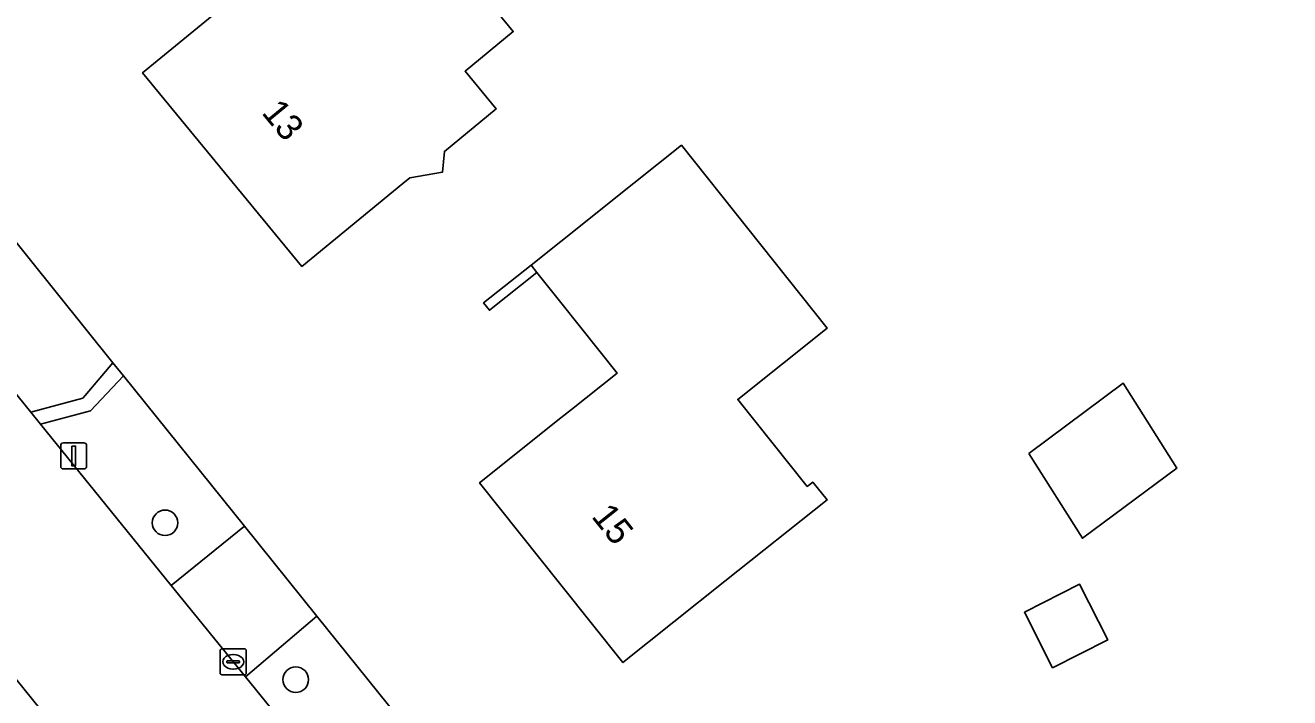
# Model space of a CAD drawing. Extents: x 162417 to 163722, y 384268 to 385417.
# Drawn here: x 163479.48 to 163527.92, y 384789.06 to 384814.82 of the extents above; entities that cross this region are included whole.
import ezdxf

# ---------------------------------------------------------------- set-up
doc = ezdxf.new("R2010")
doc.units = 0
for name, color, linetype in [('IMGEO_Berm_groen', 7, 'Continuous'), ('IMGEO_Boom', 7, 'Continuous'), ('IMGEO_Erf', 7, 'Continuous'), ('IMGEO_Kolk', 7, 'Continuous'), ('IMGEO_Lichtmast', 7, 'Continuous'), ('IMGEO_Muur', 7, 'Continuous'), ('IMGEO_Pand', 7, 'Continuous'), ('IMGEO_Pand_nummerreeks', 7, 'Continuous'), ('IMGEO_Rijbaan_lokaal_gesloten', 7, 'Continuous'), ('IMGEO_Voetpad_open', 7, 'Continuous')]:
    doc.layers.add(name, color=color, linetype=linetype)

msp = doc.modelspace()

# ---------------------------------------------------------------- linework, layer by layer
at = {"layer": 'IMGEO_Berm_groen'}
for points in [[(163478.544, 384807.238), (163475.697, 384804.93), (163479.692, 384800.002), (163481.684, 384800.531), (163481.772, 384800.634), (163482.841, 384801.894)], [(163483.251, 384801.384), (163481.978, 384800.048), (163480.069, 384799.537), (163485.075, 384793.362), (163487.878, 384795.63)], [(163490.658, 384792.176), (163487.913, 384789.862), (163497.934, 384777.502), (163500, 384778.506), (163501.192, 384779.094), (163500, 384780.574)]]:
    msp.add_lwpolyline(points, close=True, dxfattribs=at)
msp.add_lwpolyline([(163500.768, 384762.843), (163498.152, 384766.179), (163475.492, 384794.264)], dxfattribs=at)
at = {"layer": 'IMGEO_Boom'}
for centre in [(163484.838, 384795.758), (163489.844, 384789.748)]:
    msp.add_circle(centre, 0.489, dxfattribs=at)
at = {"layer": 'IMGEO_Erf'}
for points in [[(163495.537, 384809.986), (163495.46, 384809.189), (163494.212, 384808.981), (163493.944, 384808.76), (163490.082, 384805.583), (163483.976, 384813.003), (163487.76, 384816.118), (163489.245, 384817.34), (163488.402, 384818.365), (163487.45, 384818.206), (163487.125, 384818.602), (163487.08, 384818.657), (163484.691, 384821.56), (163488.553, 384824.737), (163492.118, 384827.671), (163496.846, 384821.926), (163494.033, 384819.612), (163498.173, 384814.58), (163496.328, 384813.061), (163497.518, 384811.616)], [(163506.285, 384793.52), (163502.375, 384790.402), (163500, 384793.381), (163496.883, 384797.291), (163500, 384799.776), (163500.406, 384800.099), (163502.157, 384801.496), (163500, 384804.2), (163499.081, 384805.352), (163497.265, 384803.905), (163497.042, 384804.185), (163498.857, 384805.632), (163500, 384806.543), (163502.796, 384808.772), (163504.62, 384810.226), (163510.205, 384803.221), (163506.776, 384800.487), (163509.436, 384797.15), (163509.651, 384797.321), (163510.196, 384796.638)], [(163517.928, 384798.42), (163521.541, 384801.103), (163523.592, 384797.848), (163519.979, 384795.165)], [(163519.87, 384793.404), (163520.949, 384791.273), (163518.835, 384790.203), (163517.756, 384792.333)]]:
    msp.add_lwpolyline(points, close=True, dxfattribs=at)
msp.add_lwpolyline([(163463.926, 384825.396), (163473.971, 384812.925), (163477.644, 384808.357), (163478.544, 384807.238), (163482.841, 384801.894), (163483.251, 384801.384), (163487.878, 384795.63), (163490.658, 384792.176), (163500, 384780.574), (163501.192, 384779.094), (163504.115, 384775.46), (163512.497, 384764.123), (163515.109, 384762.248), (163516.079, 384762.732), (163516.622, 384762.752), (163544.387, 384777.107), (163568.118, 384789.259), (163565.372, 384794.06), (163550.928, 384821.281)], dxfattribs=at)
at = {"layer": 'IMGEO_Kolk'}
for p, q in [((163486.948, 384790.005), (163486.948, 384790.857)), ((163487.023, 384790.931), (163487.875, 384790.931)), ((163487.436, 384790.711), (163487.461, 384790.711)), ((163487.949, 384790.857), (163487.949, 384790.005)), ((163487.207, 384790.425), (163487.207, 384790.437)), ((163487.645, 384790.388), (163487.247, 384790.388)), ((163487.25, 384790.474), (163487.648, 384790.474)), ((163487.459, 384790.151), (163487.434, 384790.151)), ((163487.691, 384790.437), (163487.691, 384790.425)), ((163487.875, 384789.931), (163487.023, 384789.931))]:
    msp.add_line(p, q, dxfattribs=at)
for points in [[(163486.948, 384790.005), (163486.948, 384790.857)], [(163487.023, 384790.931), (163487.875, 384790.931)], [(163487.949, 384790.857), (163487.949, 384790.005)], [(163487.875, 384789.931), (163487.023, 384789.931)]]:
    msp.add_lwpolyline(points, dxfattribs=at)
for centre, radius, start, end in [((163487.025, 384790.855), 0.0765, 91.552, 178.448), ((163487.025, 384790.855), 0.0765, 91.552, 178.448), ((163487.873, 384790.855), 0.0765, 1.552, 88.448), ((163487.873, 384790.855), 0.0765, 1.552, 88.448), ((163487.247, 384790.434), 0.0403, 85.8775, 175.7526), ((163487.244, 384790.424), 0.0366, 178.938, 274.7102), ((163487.648, 384790.431), 0.043, 264.8664, 352.4533), ((163487.652, 384790.436), 0.0386, 1.7309, 96.639), ((163487.025, 384790.007), 0.0765, 181.552, 268.448), ((163487.025, 384790.007), 0.0765, 181.552, 268.448), ((163487.873, 384790.007), 0.0765, 271.552, 358.448), ((163487.873, 384790.007), 0.0765, 271.552, 358.448)]:
    msp.add_arc(centre, radius, start, end, dxfattribs=at)
for centre, major_axis, ratio, start_param, end_param in [((163487.435, 384790.431), (-0.387, 0.002), 0.722429, 4.712389, 7.853982), ((163487.46, 384790.431), (-0.39, 0.002), 0.717154, 1.570796, 4.712389)]:
    msp.add_ellipse(centre, major_axis=major_axis, ratio=ratio, start_param=start_param, end_param=end_param, dxfattribs=at)
at = {"layer": 'IMGEO_Lichtmast'}
for p, q in [((163480.841, 384797.922), (163480.841, 384798.722)), ((163480.841, 384798.722), (163480.841, 384797.922)), ((163480.941, 384798.822), (163481.731, 384798.822)), ((163481.731, 384798.822), (163480.941, 384798.822)), ((163481.831, 384798.722), (163481.831, 384797.922)), ((163481.831, 384797.922), (163481.831, 384798.722)), ((163481.731, 384797.822), (163480.941, 384797.822)), ((163480.941, 384797.822), (163481.731, 384797.822))]:
    msp.add_line(p, q, dxfattribs=at)
msp.add_lwpolyline([(163481.261, 384798.697), (163481.411, 384798.697), (163481.411, 384797.947), (163481.261, 384797.947), (163481.261, 384798.697)], dxfattribs=at)
for centre, start, end in [((163480.941, 384798.722), 90, 180), ((163480.941, 384798.722), 90, 180), ((163481.731, 384798.722), 0, 90), ((163481.731, 384798.722), 360, 90), ((163480.941, 384797.922), 180, 270), ((163480.941, 384797.922), 180, 270), ((163481.731, 384797.922), 270, 0), ((163481.731, 384797.922), 270, 0)]:
    msp.add_arc(centre, 0.1, start, end, dxfattribs=at)
at = {"layer": 'IMGEO_Muur'}
msp.add_lwpolyline([(163499.081, 384805.352), (163498.857, 384805.632), (163497.042, 384804.185), (163497.265, 384803.905)], close=True, dxfattribs=at)
at = {"layer": 'IMGEO_Pand'}
for points in [[(163494.033, 384819.612), (163496.846, 384821.926), (163492.118, 384827.671), (163488.553, 384824.737), (163484.691, 384821.56), (163487.08, 384818.657), (163487.125, 384818.602), (163487.45, 384818.206), (163488.402, 384818.365), (163489.245, 384817.34), (163487.76, 384816.118), (163483.976, 384813.003), (163490.082, 384805.583), (163493.944, 384808.76), (163494.212, 384808.981), (163495.46, 384809.189), (163495.537, 384809.986), (163497.518, 384811.616), (163496.328, 384813.061), (163498.173, 384814.58)], [(163502.796, 384808.772), (163500, 384806.543), (163498.857, 384805.632), (163499.081, 384805.352), (163500, 384804.2), (163502.157, 384801.496), (163500.406, 384800.099), (163500, 384799.776), (163496.883, 384797.291), (163500, 384793.381), (163502.375, 384790.402), (163506.285, 384793.52), (163510.196, 384796.638), (163509.651, 384797.321), (163509.436, 384797.15), (163506.776, 384800.487), (163510.205, 384803.221), (163504.62, 384810.226)], [(163517.928, 384798.42), (163519.979, 384795.165), (163523.592, 384797.848), (163521.541, 384801.103)], [(163517.756, 384792.333), (163518.835, 384790.203), (163520.949, 384791.273), (163519.87, 384793.404)]]:
    msp.add_lwpolyline(points, close=True, dxfattribs=at)
at = {"layer": 'IMGEO_Rijbaan_lokaal_gesloten'}
for points in [[(163480.069, 384799.537), (163479.692, 384800.002), (163475.697, 384804.93), (163474.814, 384806.019), (163471.11, 384810.587), (163461.042, 384823.029), (163458.817, 384825.793), (163456.919, 384828.15), (163451.602, 384823.686), (163458.271, 384815.535), (163461.838, 384811.172), (163473.146, 384797.169), (163475.492, 384794.264), (163498.152, 384766.179), (163500.768, 384762.843)], [(163501.409, 384773.121), (163500, 384774.948), (163497.934, 384777.502), (163487.913, 384789.862), (163485.075, 384793.362), (163480.069, 384799.537)]]:
    msp.add_lwpolyline(points, dxfattribs=at)
at = {"layer": 'IMGEO_Voetpad_open'}
for points in [[(163483.251, 384801.384), (163482.841, 384801.894), (163481.772, 384800.634), (163481.684, 384800.531), (163479.692, 384800.002), (163480.069, 384799.537), (163481.978, 384800.048)], [(163487.913, 384789.862), (163490.658, 384792.176), (163487.878, 384795.63), (163485.075, 384793.362)]]:
    msp.add_lwpolyline(points, close=True, dxfattribs=at)

# ---------------------------------------------------------------- texts
at = {"layer": 'IMGEO_Pand_nummerreeks'}
for s, rotation, p in [('13', 309.4537, (163488.507, 384811.463)), ('15', 308.5598, (163501.142, 384795.993))]:
    msp.add_text(s, height=1, rotation=rotation, dxfattribs=at).set_placement(p)

doc.saveas('drawing.dxf')
